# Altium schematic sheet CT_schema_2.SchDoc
size 469 x 363 mm
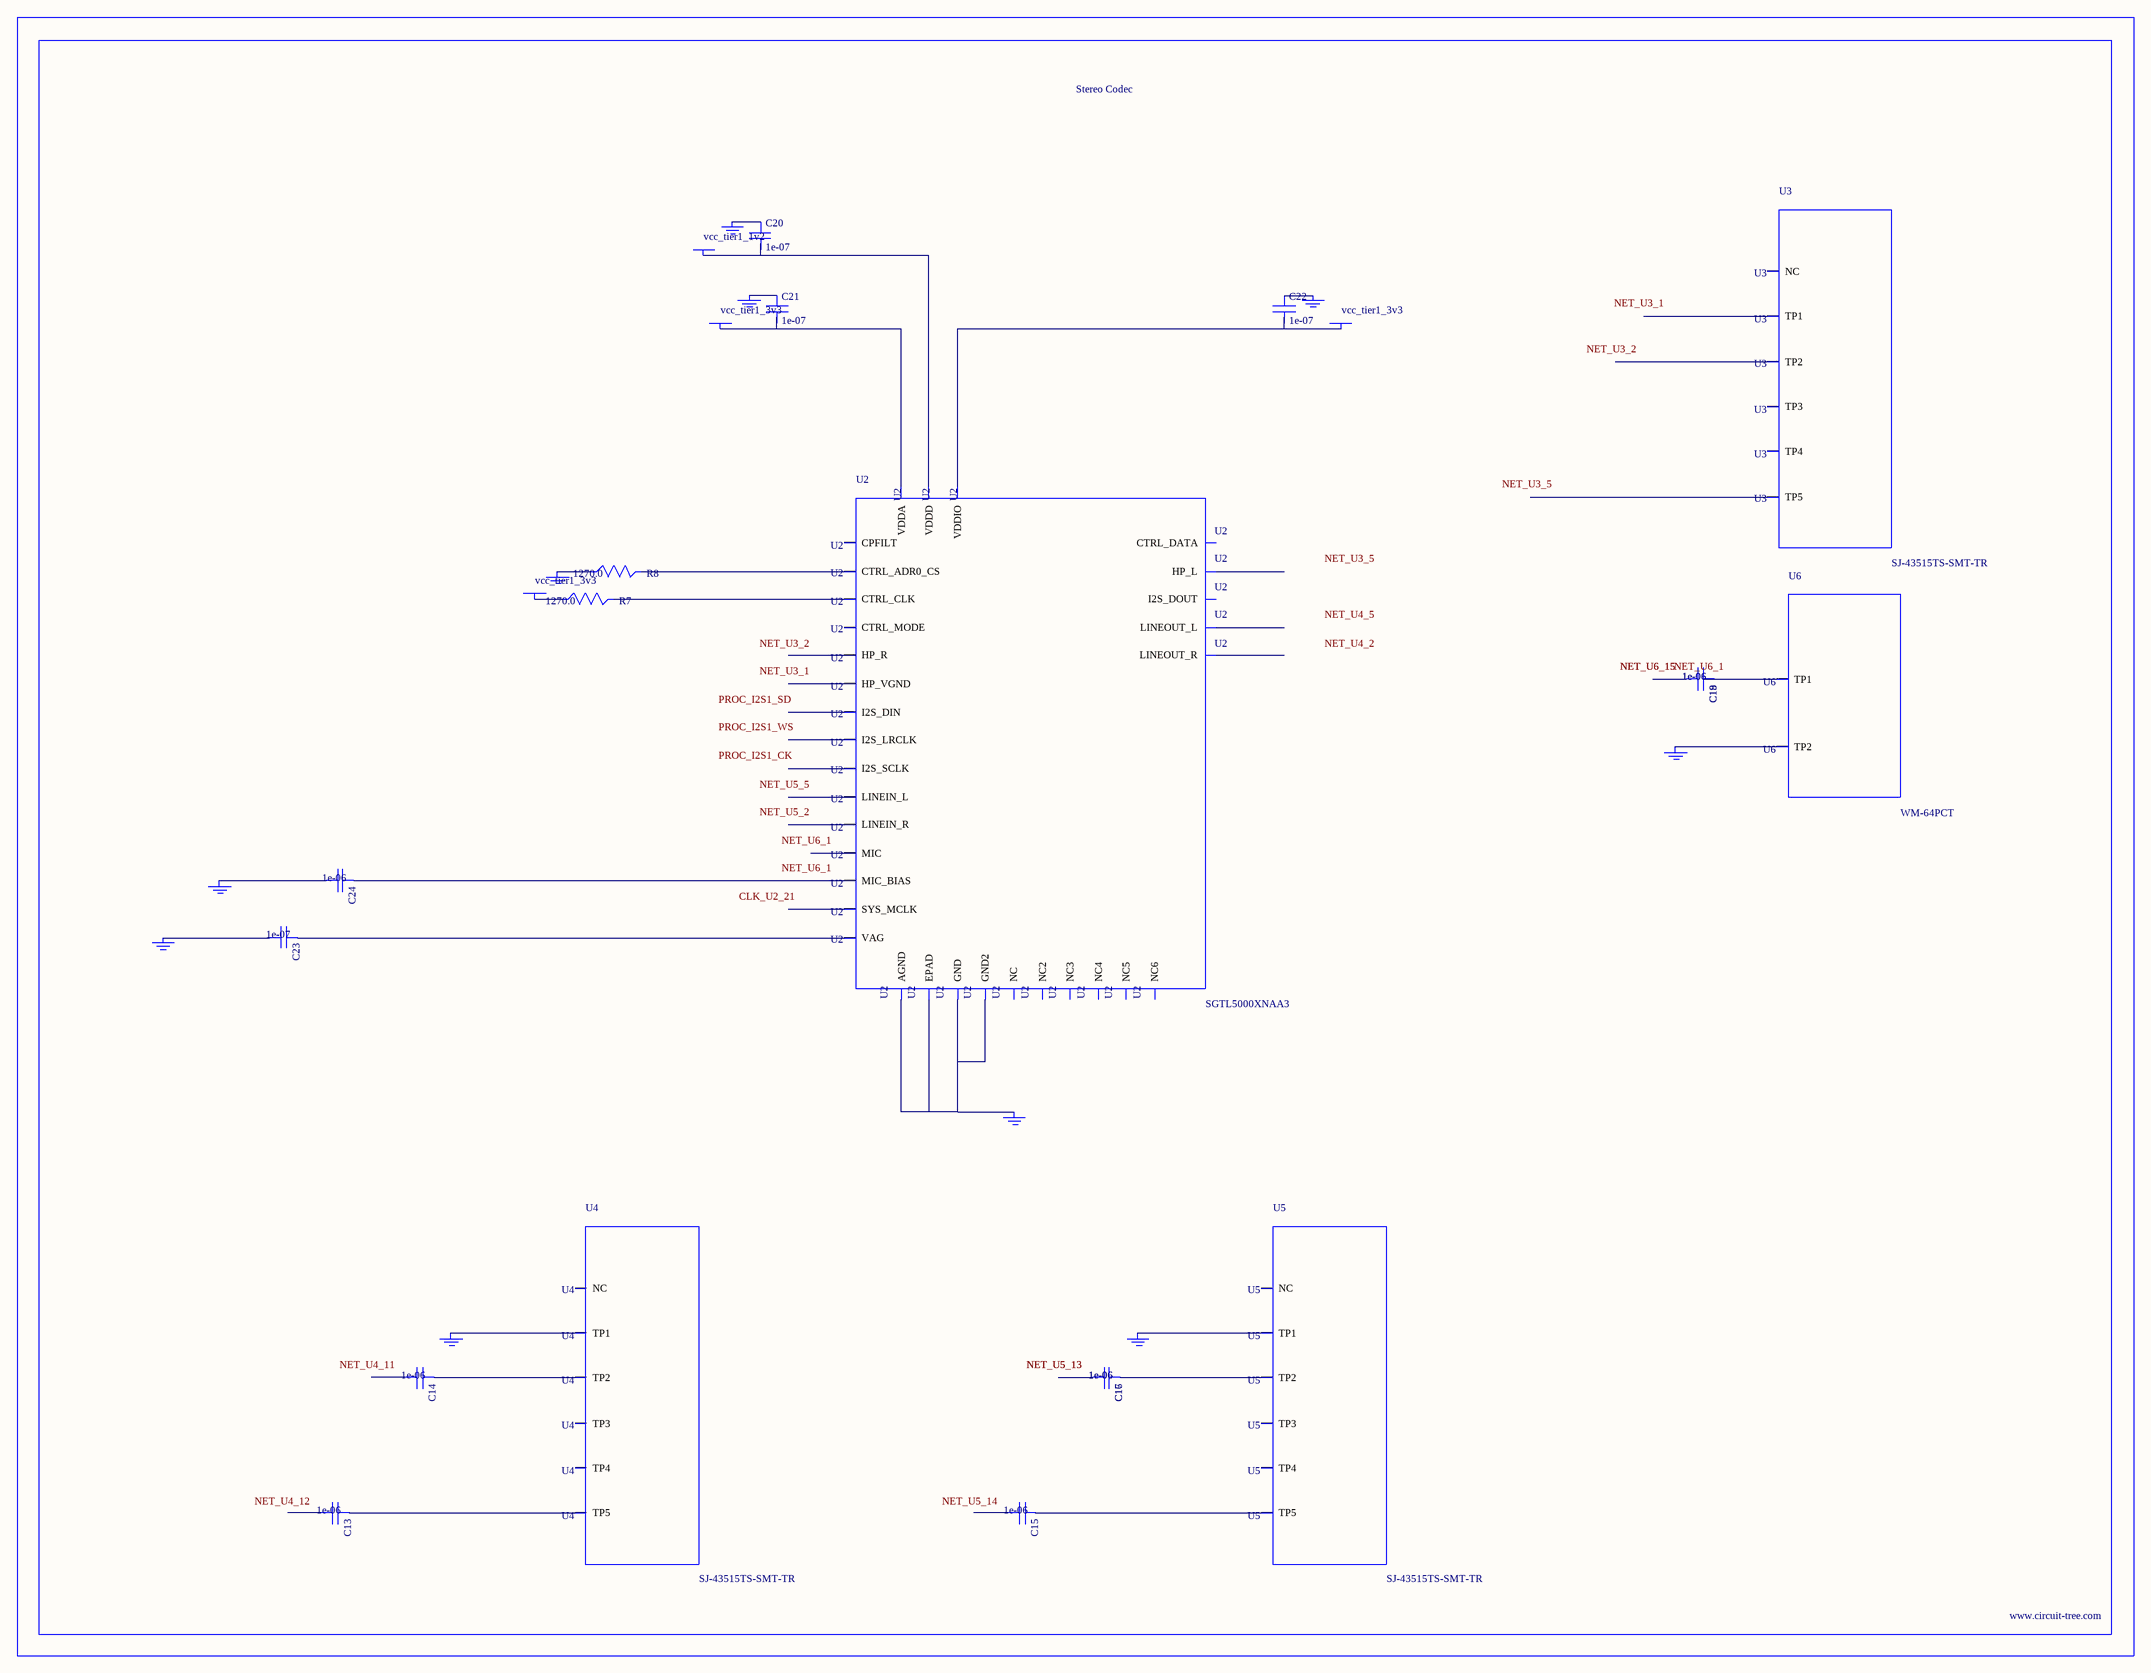
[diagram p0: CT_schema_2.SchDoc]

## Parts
BORDER1  (no value)
C13  1e-06  [C0603]
C14  1e-06  [C0603]
C15  1e-06  [C0603]
C16  1e-06  [C0603]
C17  1e-06  [C0603]
C18  1e-06  [C0603]
C19  1e-06  [C0603]
C20  1e-07  [C0402]
C21  1e-07  [C0402]
C22  1e-07  [C0402]
C23  1e-07  [C0402]
C24  1e-06  [C0603]
GND_INSTANCE_1_0  (no value)
GND_INSTANCE_1_1  (no value)
GND_INSTANCE_1_2  (no value)
GND_INSTANCE_1_3  (no value)
GND_INSTANCE_1_4  (no value)
GND_INSTANCE_1_5  (no value)
GND_INSTANCE_1_6  (no value)
GND_INSTANCE_1_7  (no value)
GND_INSTANCE_1_8  (no value)
GND_INSTANCE_1_9  (no value)
GND_INSTANCE_1_10  (no value)
POWER_INSTANCE_1_0  vcc_tier1_3v3
POWER_INSTANCE_1_1  vcc_tier1_3v3
POWER_INSTANCE_1_2  vcc_tier1_3v3
POWER_INSTANCE_1_3  vcc_tier1_1v2
R7  1270.0  [R0603]
R8  1270.0  [R0603]
U2  SGTL5000XNAA3  [QFN-32]
U3  SJ-43515TS-SMT-TR  [SJ-43515TS-SMT-TR]
U4  SJ-43515TS-SMT-TR  [SJ-43515TS-SMT-TR]
U5  SJ-43515TS-SMT-TR  [SJ-43515TS-SMT-TR]
U6  WM-64PCT  [WM-64PC]

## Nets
NetC13_1: C13.1 U4.5(TP5)
NetC14_1: C14.1 U4.2(TP2)
NetC15_1: C15.1 U5.5(TP5)
NetC16_1: C16.1 C17.1 U5.2(TP2)
NetC16_2: C16.2 C17.2
NetC18_1: C18.1 C19.1 U6.1(TP1)
NetC18_2: C18.2 C19.2
NetC20_1: C20.1 GND_INSTANCE_1_5.0(GND)
NetC20_2: C20.2 POWER_INSTANCE_1_3.0(PWR) U2.30(VDDD)
NetC21_1: C21.1 GND_INSTANCE_1_1.0(GND)
NetC21_2: C21.2 POWER_INSTANCE_1_0.0(PWR) U2.5(VDDA)
NetC22_1: C22.1 GND_INSTANCE_1_4.0(GND)
NetC22_2: C22.2 POWER_INSTANCE_1_1.0(PWR) U2.20(VDDIO)
NetC23_1: C23.1 U2.10(VAG)
NetC23_2: C23.2 GND_INSTANCE_1_2.0(GND)
NetC24_1: C24.1 U2.16(MIC_BIAS)
NetC24_2: C24.2 GND_INSTANCE_1_3.0(GND)
NetGND_INSTANCE_1_0_0: GND_INSTANCE_1_0.0(GND) U2.1(GND) U2.3(GND2) U2.7(AGND) U2.EXP(EPAD)
NetGND_INSTANCE_1_6_0: GND_INSTANCE_1_6.0(GND) R8.1
NetGND_INSTANCE_1_7_0: GND_INSTANCE_1_7.0(GND) U4.1(TP1)
NetGND_INSTANCE_1_8_0: GND_INSTANCE_1_8.0(GND) GND_INSTANCE_1_9.0(GND) U5.1(TP1)
NetGND_INSTANCE_1_10_0: GND_INSTANCE_1_10.0(GND) U6.2(TP2)
NetPOWER_INSTANCE_1_2_0: POWER_INSTANCE_1_2.0(PWR) R7.1
NetR7_2: R7.2 U2.29(CTRL_CLK)
NetR8_2: R8.2 U2.31(CTRL_ADR0_CS)

Not connected (* = marked no-connect by the designer): C13 2; C14 2; C15 2; U2 2(HP_R) 4(HP_VGND) 6(HP_L) 8(NC) 9(NC2) 11(LINEOUT_R) 12(LINEOUT_L) 13(LINEIN_R) 14(LINEIN_L) 15(MIC) 17(NC3) 18(CPFILT) 19(NC4) 21(SYS_MCLK) 22(NC5) 23(I2S_LRCLK) 24(I2S_SCLK) 25(I2S_DOUT) 26(I2S_DIN) 27(CTRL_DATA) 28(NC6) 32(CTRL_MODE); U3 1(TP1) 2(TP2) 3(TP3) 4(TP4) 5(TP5) 6(NC); U4 3(TP3) 4(TP4) 6(NC); U5 3(TP3) 4(TP4) 6(NC)

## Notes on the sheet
- Labels drawn without touching a wire or pin: CLK_U2_21, NET_U3_1, NET_U3_2, NET_U3_5, NET_U4_2, NET_U4_5, NET_U4_11, NET_U4_12, NET_U5_2, NET_U5_5, NET_U5_14, NET_U6_1, PROC_I2S1_CK, PROC_I2S1_SD, PROC_I2S1_WS

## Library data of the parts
BORDER1 = BORDER_PAGE1
C13-C19 C24 = C0603C105K3RACTU
C20-C23 = C0402C104K3RACTU
GND_INSTANCE_1_0-GND_INSTANCE_1_10 = GND
POWER_INSTANCE_1_0-POWER_INSTANCE_1_3 = PWR
R7 R8 = RC0603FR-071K27L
